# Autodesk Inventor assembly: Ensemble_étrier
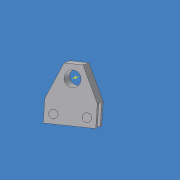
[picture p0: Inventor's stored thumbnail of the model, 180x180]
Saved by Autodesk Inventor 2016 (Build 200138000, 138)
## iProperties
Shininess: 64.0
Length Units: 11269
Angle Units: 11279
Time Units: 11290
Mass Units: 11283
Length Display Precision: 3
Angle Display Precision: 2
Compacted: True
Created: 2003-07
Part Number: Ensemble_étrier
Document SubType Name: Assembly
Designer: trameau
Density: 0.0
Volumn: 0.0
Area: 0.0
PropertySet Name: Model Information
Control State: 0
Master: False
Checked Out: False
Author: trameau
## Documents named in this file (3)
- G:\Consmec\1si\Cours\Leçon 05 - Statique\05-04-Statique avec frottement\06-02 Exercices statique Frottement\28-02 Exercices statique Frottement\28-02-02 Exercice stat frottement 2\06-02-02-2 Dessin 3d pincetole\Ensemble_étrier.iam
- G:\Consmec\1si\Cours\Leçon 05 - Statique\05-04-Statique avec frottement\06-02 Exercices statique Frottement\28-02 Exercices statique Frottement\28-02-02 Exercice stat frottement 2\06-02-02-2 Dessin 3d pincetole\étrier.ipt
- G:\Consmec\1si\Cours\Leçon 05 - Statique\05-04-Statique avec frottement\06-02 Exercices statique Frottement\28-02 Exercices statique Frottement\28-02-02 Exercice stat frottement 2\06-02-02-2 Dessin 3d pincetole\axe_10x20.ipt
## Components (3 placed, 2 different names)
1. étrier:1 — Logement:1, Logement:2
2. axe_10x20:1 — Logement:1
3. axe_10x20:2 — Logement:2
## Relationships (2: Insert 2)
- Logement:1 [Insert]: étrier:1 ↔ axe_10x20:1
- Logement:2 [Insert]: étrier:1 ↔ axe_10x20:2
